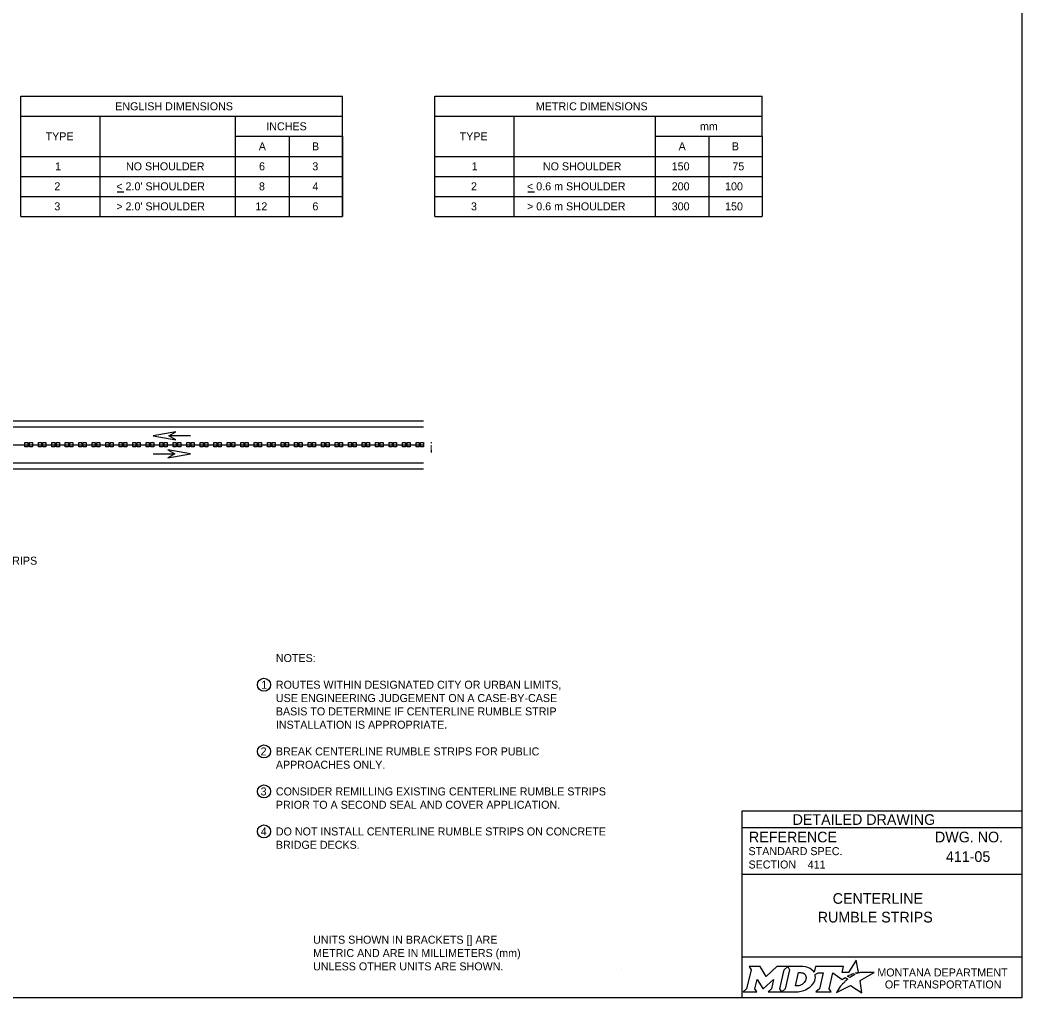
# Model space of a CAD drawing. Extents: x 49937 to 50080, y 49883 to 50108.
# Drawn here: x 50009.24 to 50016.75, y 49987.8 to 49995.13 of the extents above; entities that cross this region are included whole.
import ezdxf

# ---------------------------------------------------------------- set-up
doc = ezdxf.new("R2010")
doc.units = 0
for name, color, linetype in [('Default', 7, 'Continuous'), ('Level 1', 7, 'Continuous'), ('Level 2', 7, 'Continuous'), ('Level 5', 7, 'Continuous')]:
    doc.layers.add(name, color=color, linetype=linetype)

msp = doc.modelspace()

# ---------------------------------------------------------------- linework, layer by layer
at = {"layer": 'Default'}
for points in [[(50015.5126, 49987.9811), (50015.5023, 49987.9867), (50015.5139, 49987.9895), (50015.5255, 49987.9915), (50015.5081, 49988.0816), (50015.4486, 49987.9903), (50015.4013, 49987.9896), (50015.4116, 49988.0337), (50015.2024, 49988.0338), (50015.1923, 49987.9913), (50015.1865, 49987.9996)], [(50014.7056, 49988.0338), (50014.7197, 49988.0104), (50014.6862, 49987.8671), (50014.6605, 49987.8446), (50014.7621, 49987.8446), (50014.7486, 49987.8674), (50014.7648, 49987.9375), (50014.8085, 49987.8685), (50014.8138, 49987.8685), (50014.8889, 49987.938), (50014.8725, 49987.8669), (50014.8478, 49987.8449), (50014.9494, 49987.8449), (50014.9356, 49987.8682), (50014.9688, 49988.0106)], [(50014.9688, 49988.0106), (50014.9941, 49988.0338), (50014.9117, 49988.0338), (50014.8321, 49987.9608), (50014.7876, 49988.0335), (50014.7056, 49988.0338)], [(50015.1077, 49988.0338), (50014.9941, 49988.0338), (50015.0088, 49988.0109), (50014.9749, 49987.8671), (50014.9494, 49987.8449), (50015.06, 49987.8449)], [(50015.1317, 49987.9471), (50015.1305, 49987.939), (50015.1273, 49987.9297), (50015.1231, 49987.9215), (50015.1175, 49987.914), (50015.111, 49987.9071), (50015.1031, 49987.9008), (50015.0948, 49987.8961), (50015.0857, 49987.8922), (50015.0766, 49987.8899), (50015.0674, 49987.889), (50015.0515, 49987.889), (50015.0751, 49987.989), (50015.0911, 49987.989), (50015.0987, 49987.9884), (50015.1063, 49987.9865), (50015.1129, 49987.9835), (50015.119, 49987.9793), (50015.1238, 49987.9743), (50015.1275, 49987.9683), (50015.1302, 49987.9621), (50015.1318, 49987.9547), (50015.1318, 49987.9517), (50015.1317, 49987.9471)], [(50015.1991, 49987.9747), (50015.2237, 49987.9878), (50015.2606, 49987.9878), (50015.232, 49987.8673), (50015.2045, 49987.8446), (50015.3207, 49987.8446), (50015.3037, 49987.8675), (50015.3319, 49987.9877), (50015.4032, 49987.936), (50015.4243, 49987.9511), (50015.444, 49987.9402)], [(50015.3882, 49987.8843), (50015.3729, 49987.8599), (50015.3682, 49987.8524), (50015.3624, 49987.8438), (50015.3601, 49987.8395), (50015.4654, 49987.8926), (50015.5493, 49987.8375), (50015.5362, 49987.9302), (50015.6431, 49987.9886), (50015.5938, 49987.9894), (50015.5637, 49987.9898), (50015.5429, 49987.9901), (50015.5361, 49987.9886), (50015.5312, 49987.9874), (50015.5228, 49987.9851), (50015.5126, 49987.9811)], [(50015.4622, 49987.9535), (50015.4598, 49987.9518), (50015.4415, 49987.9614), (50015.4518, 49987.9671), (50015.4559, 49987.9693), (50015.4645, 49987.9733), (50015.4702, 49987.9759), (50015.4781, 49987.9789), (50015.4854, 49987.9816), (50015.4972, 49987.9742), (50015.4932, 49987.9721), (50015.4886, 49987.9696), (50015.4844, 49987.9674), (50015.4794, 49987.9645), (50015.4775, 49987.9634), (50015.4748, 49987.9618), (50015.4723, 49987.9604), (50015.47, 49987.9588), (50015.4674, 49987.957), (50015.4647, 49987.9552), (50015.4622, 49987.9535)], [(50015.1057, 49987.8522), (50015.1141, 49987.8548), (50015.1271, 49987.8602), (50015.1475, 49987.8712)], [(50015.4021, 49987.9004), (50015.4021, 49987.9004)]]:
    msp.add_lwpolyline(points, dxfattribs=at)
for centre, radius, start, end in [((50015.0868, 49987.9727), 0.1183, 300.91025, 339.13831), ((50015.1308, 49987.9554), 0.0709, 339.53292, 15.85821)]:
    msp.add_arc(centre, radius, start, end, dxfattribs=at)
for centre, major_axis, ratio, start_param, end_param in [((50015.1056, 49987.9864), (0.0834, -0.0037), 0.568097, 0.61298, 1.570796), ((50015.1612, 49987.9937), (0.0361, -0.0295), 0.469099, 1.225588, 1.570796), ((50015.4329, 49987.9305), (-0.0112, -0.0097), 0.021651, 3.157348, 6.283185), ((50015.0603, 49987.9932), (0, 0.1484), 0.987302, 3.139398, 3.456847), ((50015.3952, 49987.8923), (-0.00694, -0.00806), 0.008222, 0, 3.137361), ((50015.4119, 49987.9106), (-0.0098, -0.0102), 0.016458, 3.141593, 6.279097)]:
    msp.add_ellipse(centre, major_axis=major_axis, ratio=ratio, start_param=start_param, end_param=end_param, dxfattribs=at)
at = {"layer": 'Level 1'}
for p, q in [((50005.8942, 49992.1261), (50012.2641, 49992.1261)), ((50005.8942, 49992.0811), (50012.2641, 49992.0811)), ((50010.5185, 49992.0121), (50010.3559, 49992.0121)), ((50010.5185, 49992.012), (50010.3559, 49992.012)), ((50010.2377, 49991.879), (50010.4003, 49991.879)), ((50010.2377, 49991.8788), (50010.4003, 49991.8788)), ((50005.8944, 49991.8111), (50012.2641, 49991.8111)), ((50008.3661, 49991.7661), (50012.2641, 49991.7661))]:
    msp.add_line(p, q, dxfattribs=at)
for points in [[(49999.3835, 49998.9992), (50016.7501, 49998.9992), (50016.7501, 49987.7988), (49999.3835, 49987.7988)], [(50010.4079, 49992.0421), (50010.2377, 49992.0121), (50010.4079, 49991.9819), (50010.3561, 49992.0121)], [(50009.276, 49991.9629), (50009.2985, 49991.9629), (50009.2985, 49991.9292), (50009.276, 49991.9292)], [(50009.3097, 49991.9629), (50009.3322, 49991.9629), (50009.3322, 49991.9292), (50009.3097, 49991.9292)], [(50009.3771, 49991.9629), (50009.3996, 49991.9629), (50009.3996, 49991.9292), (50009.3771, 49991.9292)], [(50009.4108, 49991.9629), (50009.4333, 49991.9629), (50009.4333, 49991.9292), (50009.4108, 49991.9292)], [(50009.4782, 49991.9629), (50009.5007, 49991.9629), (50009.5007, 49991.9292), (50009.4782, 49991.9292)], [(50009.5119, 49991.9629), (50009.5344, 49991.9629), (50009.5344, 49991.9292), (50009.5119, 49991.9292)], [(50009.5793, 49991.9629), (50009.6018, 49991.9629), (50009.6018, 49991.9292), (50009.5793, 49991.9292)], [(50009.613, 49991.9629), (50009.6355, 49991.9629), (50009.6355, 49991.9292), (50009.613, 49991.9292)], [(50009.6804, 49991.9629), (50009.7029, 49991.9629), (50009.7029, 49991.9292), (50009.6804, 49991.9292)], [(50009.7141, 49991.9629), (50009.7366, 49991.9629), (50009.7366, 49991.9292), (50009.7141, 49991.9292)], [(50009.7815, 49991.9629), (50009.804, 49991.9629), (50009.804, 49991.9292), (50009.7815, 49991.9292)], [(50009.8152, 49991.9629), (50009.8377, 49991.9629), (50009.8377, 49991.9292), (50009.8152, 49991.9292)], [(50009.8826, 49991.9629), (50009.9051, 49991.9629), (50009.9051, 49991.9292), (50009.8826, 49991.9292)], [(50009.9163, 49991.9629), (50009.9388, 49991.9629), (50009.9388, 49991.9292), (50009.9163, 49991.9292)], [(50009.9837, 49991.9629), (50010.0062, 49991.9629), (50010.0062, 49991.9292), (50009.9837, 49991.9292)], [(50010.0174, 49991.9629), (50010.0399, 49991.9629), (50010.0399, 49991.9292), (50010.0174, 49991.9292)], [(50010.0848, 49991.9629), (50010.1073, 49991.9629), (50010.1073, 49991.9292), (50010.0848, 49991.9292)], [(50010.1185, 49991.9629), (50010.141, 49991.9629), (50010.141, 49991.9292), (50010.1185, 49991.9292)], [(50010.1859, 49991.9629), (50010.2084, 49991.9629), (50010.2084, 49991.9292), (50010.1859, 49991.9292)], [(50010.2196, 49991.9629), (50010.2421, 49991.9629), (50010.2421, 49991.9292), (50010.2196, 49991.9292)], [(50010.287, 49991.9629), (50010.3095, 49991.9629), (50010.3095, 49991.9292), (50010.287, 49991.9292)], [(50010.3207, 49991.9629), (50010.3432, 49991.9629), (50010.3432, 49991.9292), (50010.3207, 49991.9292)], [(50010.3483, 49991.8488), (50010.5187, 49991.8788), (50010.3483, 49991.909), (50010.4003, 49991.8788)], [(50010.3881, 49991.9629), (50010.4106, 49991.9629), (50010.4106, 49991.9292), (50010.3881, 49991.9292)], [(50010.4218, 49991.9629), (50010.4443, 49991.9629), (50010.4443, 49991.9292), (50010.4218, 49991.9292)], [(50010.4892, 49991.9629), (50010.5117, 49991.9629), (50010.5117, 49991.9292), (50010.4892, 49991.9292)], [(50010.5229, 49991.9629), (50010.5454, 49991.9629), (50010.5454, 49991.9292), (50010.5229, 49991.9292)], [(50010.5903, 49991.9629), (50010.6128, 49991.9629), (50010.6128, 49991.9292), (50010.5903, 49991.9292)], [(50010.624, 49991.9629), (50010.6465, 49991.9629), (50010.6465, 49991.9292), (50010.624, 49991.9292)], [(50010.6914, 49991.9629), (50010.7139, 49991.9629), (50010.7139, 49991.9292), (50010.6914, 49991.9292)], [(50010.7251, 49991.9629), (50010.7476, 49991.9629), (50010.7476, 49991.9292), (50010.7251, 49991.9292)], [(50010.7925, 49991.9629), (50010.815, 49991.9629), (50010.815, 49991.9292), (50010.7925, 49991.9292)], [(50010.8262, 49991.9629), (50010.8487, 49991.9629), (50010.8487, 49991.9292), (50010.8262, 49991.9292)], [(50010.8936, 49991.9629), (50010.9161, 49991.9629), (50010.9161, 49991.9292), (50010.8936, 49991.9292)], [(50010.9273, 49991.9629), (50010.9498, 49991.9629), (50010.9498, 49991.9292), (50010.9273, 49991.9292)], [(50010.9947, 49991.9629), (50011.0172, 49991.9629), (50011.0172, 49991.9292), (50010.9947, 49991.9292)], [(50011.0284, 49991.9629), (50011.0509, 49991.9629), (50011.0509, 49991.9292), (50011.0284, 49991.9292)], [(50011.0958, 49991.9629), (50011.1183, 49991.9629), (50011.1183, 49991.9292), (50011.0958, 49991.9292)], [(50011.1295, 49991.9629), (50011.152, 49991.9629), (50011.152, 49991.9292), (50011.1295, 49991.9292)], [(50011.1969, 49991.9629), (50011.2194, 49991.9629), (50011.2194, 49991.9292), (50011.1969, 49991.9292)], [(50011.2306, 49991.9629), (50011.2531, 49991.9629), (50011.2531, 49991.9292), (50011.2306, 49991.9292)], [(50011.298, 49991.9629), (50011.3205, 49991.9629), (50011.3205, 49991.9292), (50011.298, 49991.9292)], [(50011.3317, 49991.9629), (50011.3542, 49991.9629), (50011.3542, 49991.9292), (50011.3317, 49991.9292)], [(50011.3991, 49991.9629), (50011.4216, 49991.9629), (50011.4216, 49991.9292), (50011.3991, 49991.9292)], [(50011.4328, 49991.9629), (50011.4553, 49991.9629), (50011.4553, 49991.9292), (50011.4328, 49991.9292)], [(50011.5002, 49991.9629), (50011.5227, 49991.9629), (50011.5227, 49991.9292), (50011.5002, 49991.9292)], [(50011.5339, 49991.9629), (50011.5564, 49991.9629), (50011.5564, 49991.9292), (50011.5339, 49991.9292)], [(50011.6013, 49991.9629), (50011.6238, 49991.9629), (50011.6238, 49991.9292), (50011.6013, 49991.9292)], [(50011.635, 49991.9629), (50011.6575, 49991.9629), (50011.6575, 49991.9292), (50011.635, 49991.9292)], [(50011.7024, 49991.9629), (50011.7249, 49991.9629), (50011.7249, 49991.9292), (50011.7024, 49991.9292)], [(50011.7361, 49991.9629), (50011.7586, 49991.9629), (50011.7586, 49991.9292), (50011.7361, 49991.9292)], [(50011.8035, 49991.9629), (50011.826, 49991.9629), (50011.826, 49991.9292), (50011.8035, 49991.9292)], [(50011.8372, 49991.9629), (50011.8597, 49991.9629), (50011.8597, 49991.9292), (50011.8372, 49991.9292)], [(50011.9046, 49991.9629), (50011.9271, 49991.9629), (50011.9271, 49991.9292), (50011.9046, 49991.9292)], [(50011.9383, 49991.9629), (50011.9608, 49991.9629), (50011.9608, 49991.9292), (50011.9383, 49991.9292)], [(50012.0057, 49991.9629), (50012.0282, 49991.9629), (50012.0282, 49991.9292), (50012.0057, 49991.9292)], [(50012.0394, 49991.9629), (50012.0619, 49991.9629), (50012.0619, 49991.9292), (50012.0394, 49991.9292)], [(50012.1068, 49991.9629), (50012.1293, 49991.9629), (50012.1293, 49991.9292), (50012.1068, 49991.9292)], [(50012.1405, 49991.9629), (50012.163, 49991.9629), (50012.163, 49991.9292), (50012.1405, 49991.9292)], [(50012.2079, 49991.9629), (50012.2304, 49991.9629), (50012.2304, 49991.9292), (50012.2079, 49991.9292)], [(50012.2416, 49991.9629), (50012.2641, 49991.9629), (50012.2641, 49991.9292), (50012.2416, 49991.9292)]]:
    msp.add_lwpolyline(points, close=True, dxfattribs=at)
at = {"layer": 'Level 2'}
for p, q in [((50009.2447, 49994.5582), (50011.6559, 49994.5582)), ((50009.2447, 49993.6582), (50009.2447, 49994.5582)), ((50011.6559, 49993.6582), (50011.6559, 49994.5582)), ((50012.3483, 49994.5582), (50014.8029, 49994.5582)), ((50012.3483, 49993.6582), (50012.3483, 49994.5582)), ((50014.8029, 49994.2582), (50014.8029, 49994.5582)), ((50009.2447, 49994.4082), (50011.6559, 49994.4082)), ((50010.8559, 49993.6582), (50010.8559, 49994.4082)), ((50012.3483, 49994.4082), (50014.8029, 49994.4082)), ((50014.0029, 49993.6582), (50014.0029, 49994.4082)), ((50010.8559, 49994.2582), (50011.6559, 49994.2582)), ((50011.2559, 49994.2582), (50011.2559, 49993.6582)), ((50011.6559, 49994.2582), (50011.6559, 49993.6582)), ((50014.0029, 49994.2582), (50014.8029, 49994.2582)), ((50014.4029, 49994.2582), (50014.4029, 49993.6582)), ((50014.8029, 49994.2582), (50014.8029, 49993.6582)), ((50009.2447, 49994.1082), (50011.6559, 49994.1082)), ((50009.2447, 49994.1082), (50009.8384, 49994.1082)), ((50012.3483, 49994.1082), (50012.9419, 49994.1082)), ((50012.9419, 49994.1082), (50014.8029, 49994.1082)), ((50009.2447, 49993.9582), (50011.6559, 49993.9582)), ((50012.3483, 49993.9582), (50014.8029, 49993.9582)), ((50009.2447, 49993.8082), (50011.6559, 49993.8082)), ((50009.9686, 49993.8431), (50010.0189, 49993.8431)), ((50012.3483, 49993.8082), (50014.8029, 49993.8082)), ((50013.0471, 49993.8431), (50013.0973, 49993.8431)), ((50009.2447, 49993.6582), (50011.6559, 49993.6582)), ((50012.3483, 49993.6582), (50014.8029, 49993.6582)), ((50013.7461, 49988.0122), (50013.7461, 49988.0122))]:
    msp.add_line(p, q, dxfattribs=at)
for points in [[(50009.8384, 49994.4082), (50009.8384, 49994.2582), (50009.8384, 49994.1082), (50009.8384, 49993.9582), (50009.8384, 49993.6582)], [(50012.9419, 49994.4082), (50012.9419, 49994.2582), (50012.9419, 49994.1082), (50012.9419, 49993.9582), (50012.9419, 49993.6582)], [(50012.9419, 49994.4082), (50012.9419, 49994.2582), (50012.9419, 49994.1082), (50012.9419, 49993.9582), (50012.9419, 49993.6582)]]:
    msp.add_lwpolyline(points, dxfattribs=at)
for centre in [(50011.0683, 49990.1471), (50011.0683, 49989.6471), (50011.0683, 49989.3471), (50011.0683, 49989.0471)]:
    msp.add_circle(centre, 0.0491, dxfattribs=at)
at = {"layer": 'Level 5'}
for p, q in [((50005.8942, 49991.9461), (50012.2641, 49991.9461)), ((50016.7501, 49989.1988), (50014.6501, 49989.1988)), ((50014.6501, 49989.1988), (50014.6501, 49987.7988)), ((50016.7501, 49989.0738), (50014.6501, 49989.0738)), ((50016.3862, 49988.8587), (50016.3862, 49988.8587)), ((50015.1444, 49988.7993), (50015.1444, 49988.7993)), ((50016.7501, 49988.7238), (50014.6501, 49988.7238)), ((50015.7001, 49988.4747), (50015.7001, 49988.4747)), ((50016.7501, 49988.1057), (50014.6501, 49988.1057))]:
    msp.add_line(p, q, dxfattribs=at)

# ---------------------------------------------------------------- texts
at = {"layer": 'Default'}
for s, p in [('MONTANA DEPARTMENT', (50015.6663, 49987.96)), ('OF TRANSPORTATION', (50015.7225, 49987.87))]:
    msp.add_text(s, height=0.06, dxfattribs=at).set_placement(p)
at = {"layer": 'Level 2'}
for s, height, p in [('ENGLISH DIMENSIONS', 0.06, (50009.9531, 49994.4532)), ('METRIC DIMENSIONS', 0.06, (50013.1063, 49994.4532)), ('INCHES', 0.06, (50011.0857, 49994.3032)), ('mm', 0.06, (50014.3364, 49994.3032)), ('TYPE', 0.06, (50009.4314, 49994.2282)), ('TYPE', 0.06, (50012.535, 49994.2282)), ('A', 0.06, (50011.0292, 49994.1532)), ('B', 0.06, (50011.4281, 49994.1532)), ('A', 0.06, (50014.1762, 49994.1532)), ('B', 0.06, (50014.5752, 49994.1532)), ('1', 0.06, (50009.5024, 49994.0032)), ('NO SHOULDER', 0.06, (50010.0339, 49994.0032)), ('6', 0.06, (50011.0313, 49994.0032)), ('3', 0.06, (50011.4307, 49994.0032)), ('1', 0.06, (50012.6254, 49994.0032)), ('NO SHOULDER', 0.06, (50013.1592, 49994.0032)), ('150', 0.06, (50014.1247, 49994.0032)), ('75', 0.06, (50014.5794, 49994.0032)), ('2', 0.06, (50009.497, 49993.8532)), ("< 2.0' SHOULDER", 0.06, (50009.9614, 49993.8532)), ('8', 0.06, (50011.0309, 49993.8532)), ('4', 0.06, (50011.4319, 49993.8532)), ('2', 0.06, (50012.62, 49993.8532)), ('< 0.6 m SHOULDER', 0.06, (50013.0402, 49993.8532)), ('200', 0.06, (50014.1247, 49993.8532)), ('100', 0.06, (50014.5247, 49993.8532)), ('3', 0.06, (50009.497, 49993.7032)), ("> 2.0' SHOULDER", 0.06, (50009.9614, 49993.7032)), ('12', 0.06, (50011.0038, 49993.7032)), ('6', 0.06, (50011.4313, 49993.7032)), ('3', 0.06, (50012.6199, 49993.7032)), ('> 0.6 m SHOULDER', 0.06, (50013.0402, 49993.7032)), ('300', 0.06, (50014.1247, 49993.7032)), ('150', 0.06, (50014.5247, 49993.7032)), ('¡', 0.08, (50012.3041, 49991.9061)), ('NO RUMBLE STRIPS', 0.06, (50008.5795, 49991.0468)), ('NOTES:', 0.06, (50011.1574, 49990.3171)), ('1', 0.06, (50011.0485, 49990.1171)), ('ROUTES WITHIN DESIGNATED CITY OR URBAN LIMITS,', 0.06, (50011.1574, 49990.1171)), ('USE ENGINEERING JUDGEMENT ON A CASE-BY-CASE', 0.06, (50011.1574, 49990.0171)), ('BASIS TO DETERMINE IF CENTERLINE RUMBLE STRIP ', 0.06, (50011.1574, 49989.9171)), ('INSTALLATION IS APPROPRIATE.', 0.06, (50011.1574, 49989.8171)), ('2', 0.06, (50011.0431, 49989.6171)), ('BREAK CENTERLINE RUMBLE STRIPS FOR PUBLIC', 0.06, (50011.1574, 49989.6171)), ('APPROACHES ONLY.', 0.06, (50011.1574, 49989.5171)), ('3', 0.06, (50011.0431, 49989.3171)), ('CONSIDER REMILLING EXISTING CENTERLINE RUMBLE STRIPS', 0.06, (50011.1574, 49989.3171)), ('PRIOR TO A SECOND SEAL AND COVER APPLICATION.', 0.06, (50011.1574, 49989.2171)), ('4', 0.06, (50011.0443, 49989.0171)), ('DO NOT INSTALL CENTERLINE RUMBLE STRIPS ON CONCRETE', 0.06, (50011.1574, 49989.0171)), ('BRIDGE DECKS.', 0.06, (50011.1574, 49988.9171)), ('411-05', 0.08, (50016.1798, 49988.8187)), ('411', 0.06, (50015.1444, 49988.7693)), ('CENTERLINE', 0.08, (50015.3314, 49988.5047)), ('RUMBLE STRIPS', 0.08, (50015.2193, 49988.3647)), ('UNITS SHOWN IN BRACKETS [] ARE ', 0.06, (50011.4365, 49988.2056)), ('METRIC AND ARE IN MILLIMETERS (mm) ', 0.06, (50011.4365, 49988.1056)), ('UNLESS OTHER UNITS ARE SHOWN.', 0.06, (50011.4365, 49988.0056))]:
    msp.add_text(s, height=height, dxfattribs=at).set_placement(p)
at = {"layer": 'Level 5'}
for s, height, p in [('DETAILED DRAWING', 0.0799, (50015.0311, 49989.0963)), ('REFERENCE', 0.08, (50014.7037, 49988.9654)), ('DWG. NO.', 0.08, (50016.0979, 49988.9654)), ('STANDARD SPEC.', 0.06, (50014.7004, 49988.8694)), ('SECTION', 0.06, (50014.7004, 49988.7694))]:
    msp.add_text(s, height=height, dxfattribs=at).set_placement(p)

doc.saveas('drawing.dxf')
